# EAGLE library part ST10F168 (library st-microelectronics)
MICROCONTROLLER with CAN 2.0B INTERFACE Siemens compatible
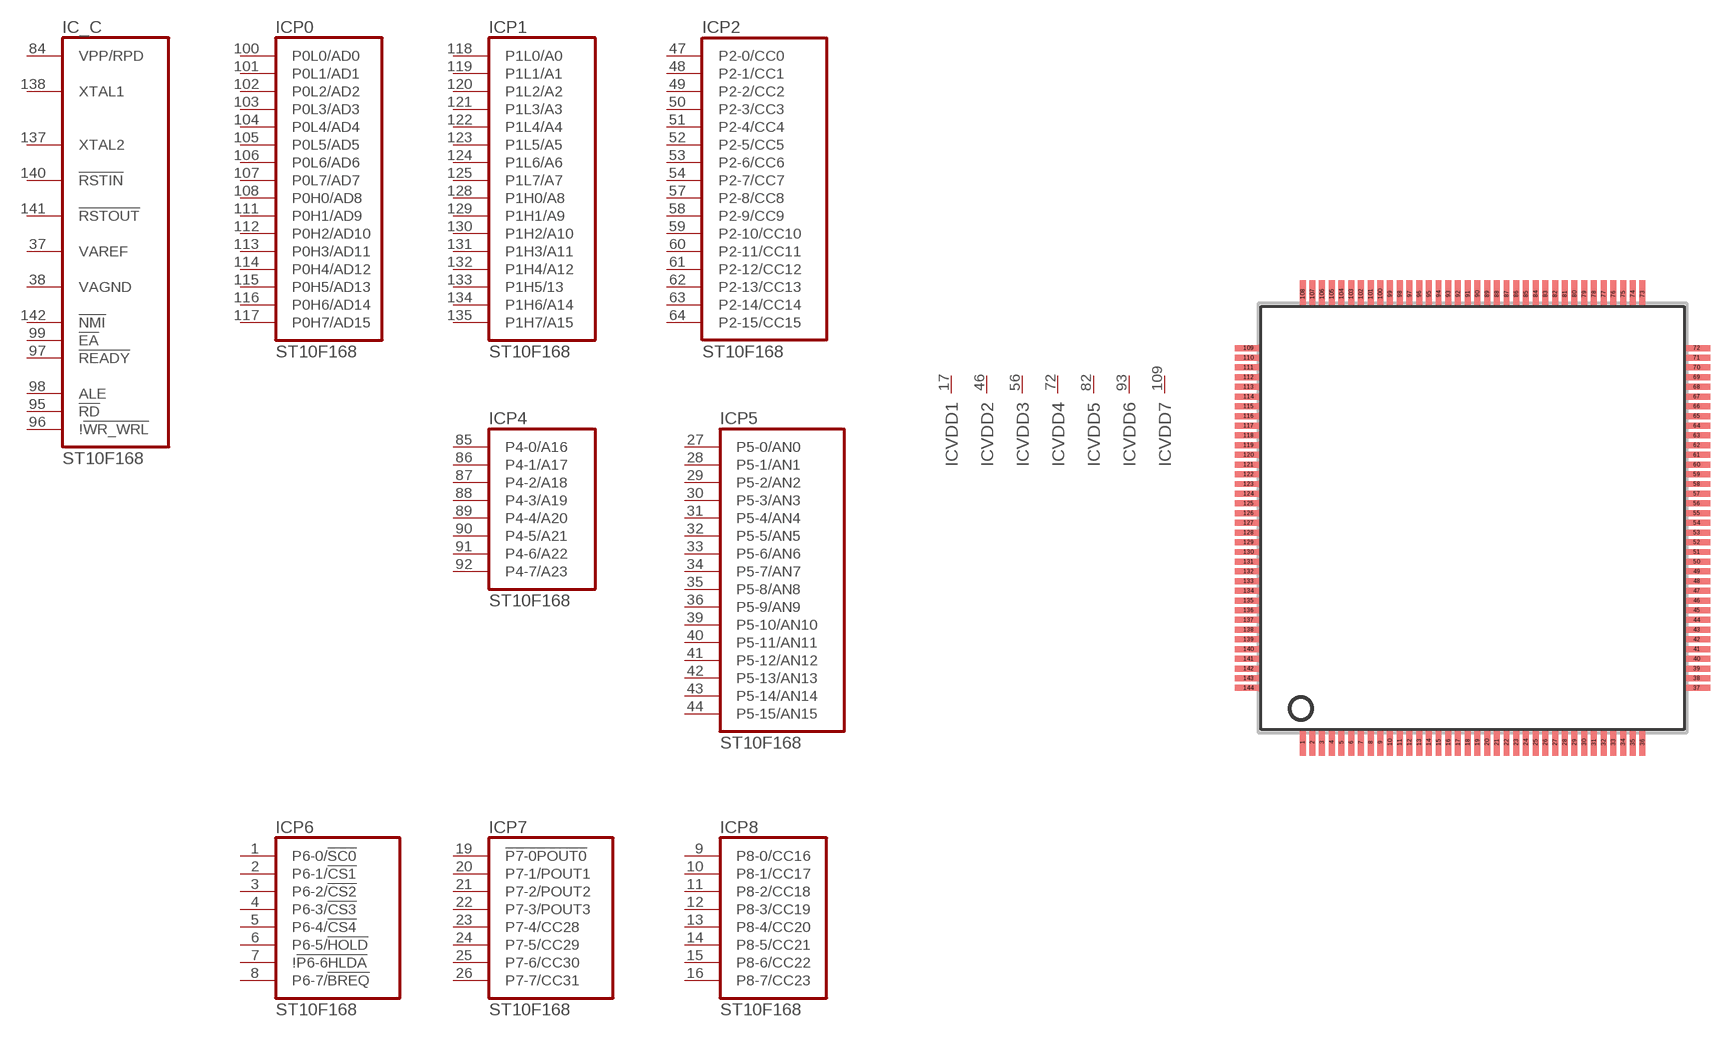
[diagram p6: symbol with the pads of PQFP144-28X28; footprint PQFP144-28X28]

Designator prefix IC; gates _C=F168_C P0=F168_P0 P1=F168_P1 P2=F168_P2 P4=F168_P4 P5=F168_P5 P6=F168_P6 P7=F168_P7 P8=F168_P8 VDD1=VDD VDD2=VDD VDD3=VDD VDD4=VDD VDD5=VDD VDD6=VDD VDD7=VDD VDD8=VDD VDD9=VDD VDD10=VDD VSS1=VSS VSS2=VSS VSS3=VSS VSS4=VSS VSS5=VSS VSS6=VSS VSS7=VSS VSS8=VSS VSS9=VSS VSS10=VSS P3=F168_P3

## ST10F168 (MPN: ST10F168SQ6/TR; OC_FARNELL: 1796092; OC_NEWARK: 37M7384)  [PQFP144-28X28]
1  P6:P6-0/!SC0
2  P6:P6-1/!CS1
3  P6:P6-2/!CS2
4  P6:P6-3/!CS3
5  P6:P6-4/!CS4
6  P6:P6-5/!HOLD
7  P6:!!P6-6HLDA
8  P6:P6-7/!BREQ
9  P8:P8-0/CC16
10  P8:P8-1/CC17
11  P8:P8-2/CC18
12  P8:P8-3/CC19
13  P8:P8-4/CC20
14  P8:P8-5/CC21
15  P8:P8-6/CC22
16  P8:P8-7/CC23
17  VDD1:VDD  pwr
18  VSS1:VSS  pwr
19  P7:!P7-0POUT0
20  P7:P7-1/POUT1
21  P7:P7-2/POUT2
22  P7:P7-3/POUT3
23  P7:P7-4/CC28
24  P7:P7-5/CC29
25  P7:P7-6/CC30
26  P7:P7-7/CC31
27  P5:P5-0/AN0  in
28  P5:P5-1/AN1  in
29  P5:P5-2/AN2  in
30  P5:P5-3/AN3  in
31  P5:P5-4/AN4  in
32  P5:P5-5/AN5  in
33  P5:P5-6/AN6  in
34  P5:P5-7/AN7  in
35  P5:P5-8/AN8  in
36  P5:P5-9/AN9  in
37  _C:VAREF  pas
38  _C:VAGND  pas
39  P5:P5-10/AN10  in
40  P5:P5-11/AN11  in
41  P5:P5-12/AN12  in
42  P5:P5-13/AN13  in
43  P5:P5-14/AN14  in
44  P5:P5-15/AN15  in
45  VSS2:VSS  pwr
46  VDD2:VDD  pwr
47  P2:P2-0/CC0
48  P2:P2-1/CC1
49  P2:P2-2/CC2
50  P2:P2-3/CC3
51  P2:P2-4/CC4
52  P2:P2-5/CC5
53  P2:P2-6/CC6
54  P2:P2-7/CC7
55  VSS3:VSS  pwr
56  VDD3:VDD  pwr
57  P2:P2-8/CC8
58  P2:P2-9/CC9
59  P2:P2-10/CC10
60  P2:P2-11/CC11
61  P2:P2-12/CC12
62  P2:P2-13/CC13
63  P2:P2-14/CC14
64  P2:P2-15/CC15
65  P3:P3-0/TOIN
66  P3:P3-1/T6OUT
67  P3:P3-2/CAPIN
68  P3:P3-3/T3OUT
69  P3:P3-4/T3EUD
70  P3:P3-5/T4IN
71  VSS4:VSS  pwr
72  VDD4:VDD  pwr
73  P3:P3-6/T3IN
74  P3:P3-7/T2IN
75  P3:P3-8/MRST
76  P3:P3-9/MTSR
77  P3:P3-10/TXD0
78  P3:P3-11/RXD0
79  P3:P3-12/!BHE
80  P3:P3-13/SCLK
81  P3:P3-15/CLKO
82  VDD5:VDD  pwr
83  VSS5:VSS  pwr
84  _C:VPP/RPD  in
85  P4:P4-0/A16
86  P4:P4-1/A17
87  P4:P4-2/A18
88  P4:P4-3/A19
89  P4:P4-4/A20
90  P4:P4-5/A21
91  P4:P4-6/A22
92  P4:P4-7/A23
93  VDD6:VDD  pwr
94  VSS6:VSS  pwr
95  _C:!RD  out
96  _C:!!WR_WRL  out
97  _C:!READY  in
98  _C:ALE  out
99  _C:!EA  in
100  P0:P0L0/AD0
101  P0:P0L1/AD1
102  P0:P0L2/AD2
103  P0:P0L3/AD3
104  P0:P0L4/AD4
105  P0:P0L5/AD5
106  P0:P0L6/AD6
107  P0:P0L7/AD7
108  P0:P0H0/AD8
109  VDD7:VDD  pwr
110  VSS7:VSS  pwr
111  P0:P0H1/AD9
112  P0:P0H2/AD10
113  P0:P0H3/AD11
114  P0:P0H4/AD12
115  P0:P0H5/AD13
116  P0:P0H6/AD14
117  P0:P0H7/AD15
118  P1:P1L0/A0
119  P1:P1L1/A1
120  P1:P1L2/A2
121  P1:P1L3/A3
122  P1:P1L4/A4
123  P1:P1L5/A5
124  P1:P1L6/A6
125  P1:P1L7/A7
126  VDD8:VDD  pwr
127  VSS8:VSS  pwr
128  P1:P1H0/A8
129  P1:P1H1/A9
130  P1:P1H2/A10
131  P1:P1H3/A11
132  P1:P1H4/A12
133  P1:P1H5/13
134  P1:P1H6/A14
135  P1:P1H7/A15
136  VDD9:VDD  pwr
137  _C:XTAL2  out
138  _C:XTAL1  in
139  VSS9:VSS  pwr
140  _C:!RSTIN  in
141  _C:!RSTOUT  out
142  _C:!NMI  in
143  VSS10:VSS  pwr
144  VDD10:VDD  pwr

## Footprint PQFP144-28X28 (pad centres in mm)
Plastic Quad Flat Pack
smd 0.4 x 1.8: 1 -11.375,-15; 2 -10.725,-15; 3 -10.075,-15; 4 -9.425,-15; 5 -8.775,-15; 6 -8.125,-15; 7 -7.475,-15; 8 -6.825,-15; 9 -6.175,-15; 10 -5.525,-15; 11 -4.875,-15; 12 -4.225,-15; 13 -3.575,-15; 14 -2.925,-15; 15 -2.275,-15; 16 -1.625,-15; 17 -0.975,-15; 18 -0.325,-15; 19 0.325,-15; 20 0.975,-15; 21 1.625,-15; 22 2.275,-15; 23 2.925,-15; 24 3.575,-15; 25 4.225,-15; 26 4.875,-15; 27 5.525,-15; 28 6.175,-15; 29 6.825,-15; 30 7.475,-15; 31 8.125,-15; 32 8.775,-15; 33 9.425,-15; 34 10.075,-15; 35 10.725,-15; 36 11.375,-15; 73 11.375,15; 74 10.725,15; 75 10.075,15; 76 9.425,15; 77 8.775,15; 78 8.125,15; 79 7.475,15; 80 6.825,15; 81 6.175,15; 82 5.525,15; 83 4.875,15; 84 4.225,15; 85 3.575,15; 86 2.925,15; 87 2.275,15; 88 1.625,15; 89 0.975,15; 90 0.325,15; 91 -0.325,15; 92 -0.975,15; 93 -1.625,15; 94 -2.275,15; 95 -2.925,15; 96 -3.575,15; 97 -4.225,15; 98 -4.875,15; 99 -5.525,15; 100 -6.175,15; 101 -6.825,15; 102 -7.475,15; 103 -8.125,15; 104 -8.775,15; 105 -9.425,15; 106 -10.075,15; 107 -10.725,15; 108 -11.375,15
smd 1.8 x 0.4: 37 15,-11.375; 38 15,-10.725; 39 15,-10.075; 40 15,-9.425; 41 15,-8.775; 42 15,-8.125; 43 15,-7.475; 44 15,-6.825; 45 15,-6.175; 46 15,-5.525; 47 15,-4.875; 48 15,-4.225; 49 15,-3.575; 50 15,-2.925; 51 15,-2.275; 52 15,-1.625; 53 15,-0.975; 54 15,-0.325; 55 15,0.325; 56 15,0.975; 57 15,1.625; 58 15,2.275; 59 15,2.925; 60 15,3.575; 61 15,4.225; 62 15,4.875; 63 15,5.525; 64 15,6.175; 65 15,6.825; 66 15,7.475; 67 15,8.125; 68 15,8.775; 69 15,9.425; 70 15,10.075; 71 15,10.725; 72 15,11.375; 109 -15,11.375; 110 -15,10.725; 111 -15,10.075; 112 -15,9.425; 113 -15,8.775; 114 -15,8.125; 115 -15,7.475; 116 -15,6.825; 117 -15,6.175; 118 -15,5.525; 119 -15,4.875; 120 -15,4.225; 121 -15,3.575; 122 -15,2.925; 123 -15,2.275; 124 -15,1.625; 125 -15,0.975; 126 -15,0.325; 127 -15,-0.325; 128 -15,-0.975; 129 -15,-1.625; 130 -15,-2.275; 131 -15,-2.925; 132 -15,-3.575; 133 -15,-4.225; 134 -15,-4.875; 135 -15,-5.525; 136 -15,-6.175; 137 -15,-6.825; 138 -15,-7.475; 139 -15,-8.125; 140 -15,-8.775; 141 -15,-9.425; 142 -15,-10.075; 143 -15,-10.725; 144 -15,-11.375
